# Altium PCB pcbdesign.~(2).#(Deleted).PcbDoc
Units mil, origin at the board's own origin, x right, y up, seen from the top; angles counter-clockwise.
Board outline 6000 x 4000 mil, 2 copper layers (Top Layer, Bottom Layer); 15 components, 13 nets, 60 pads, 0 vias.
Unrouted connection lines stored in the file: 20.
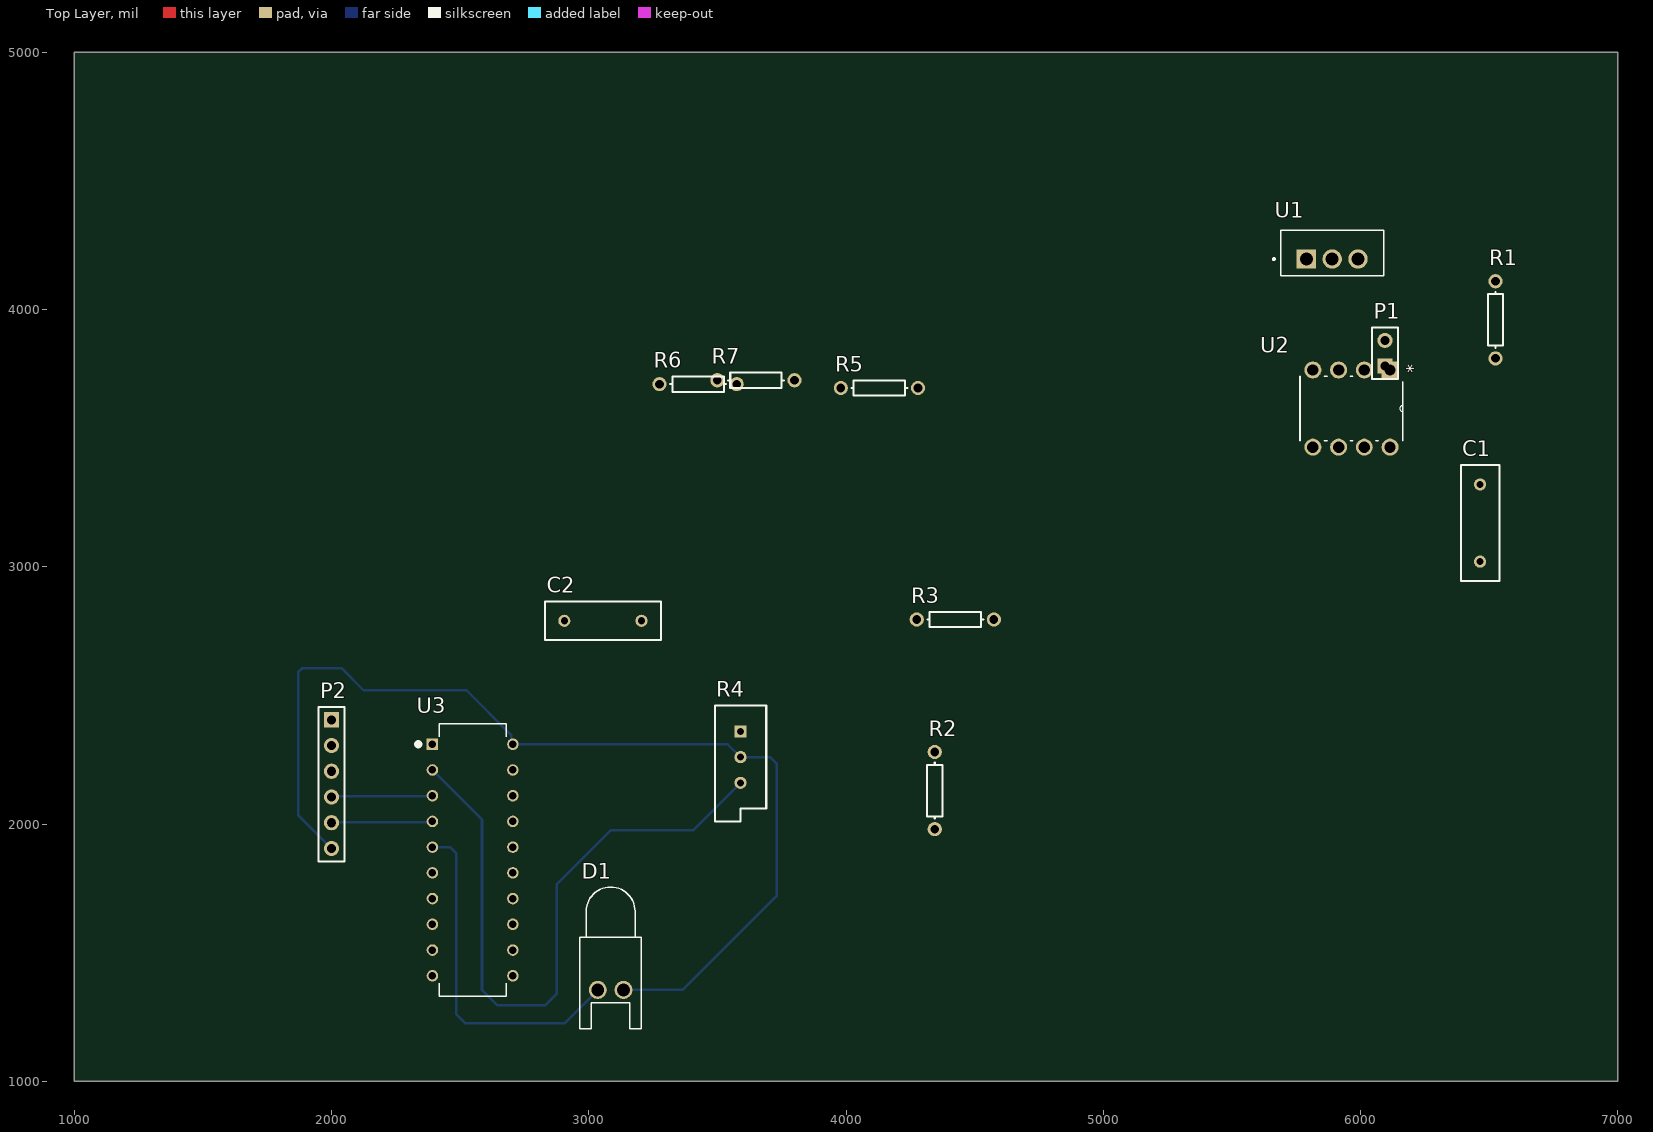
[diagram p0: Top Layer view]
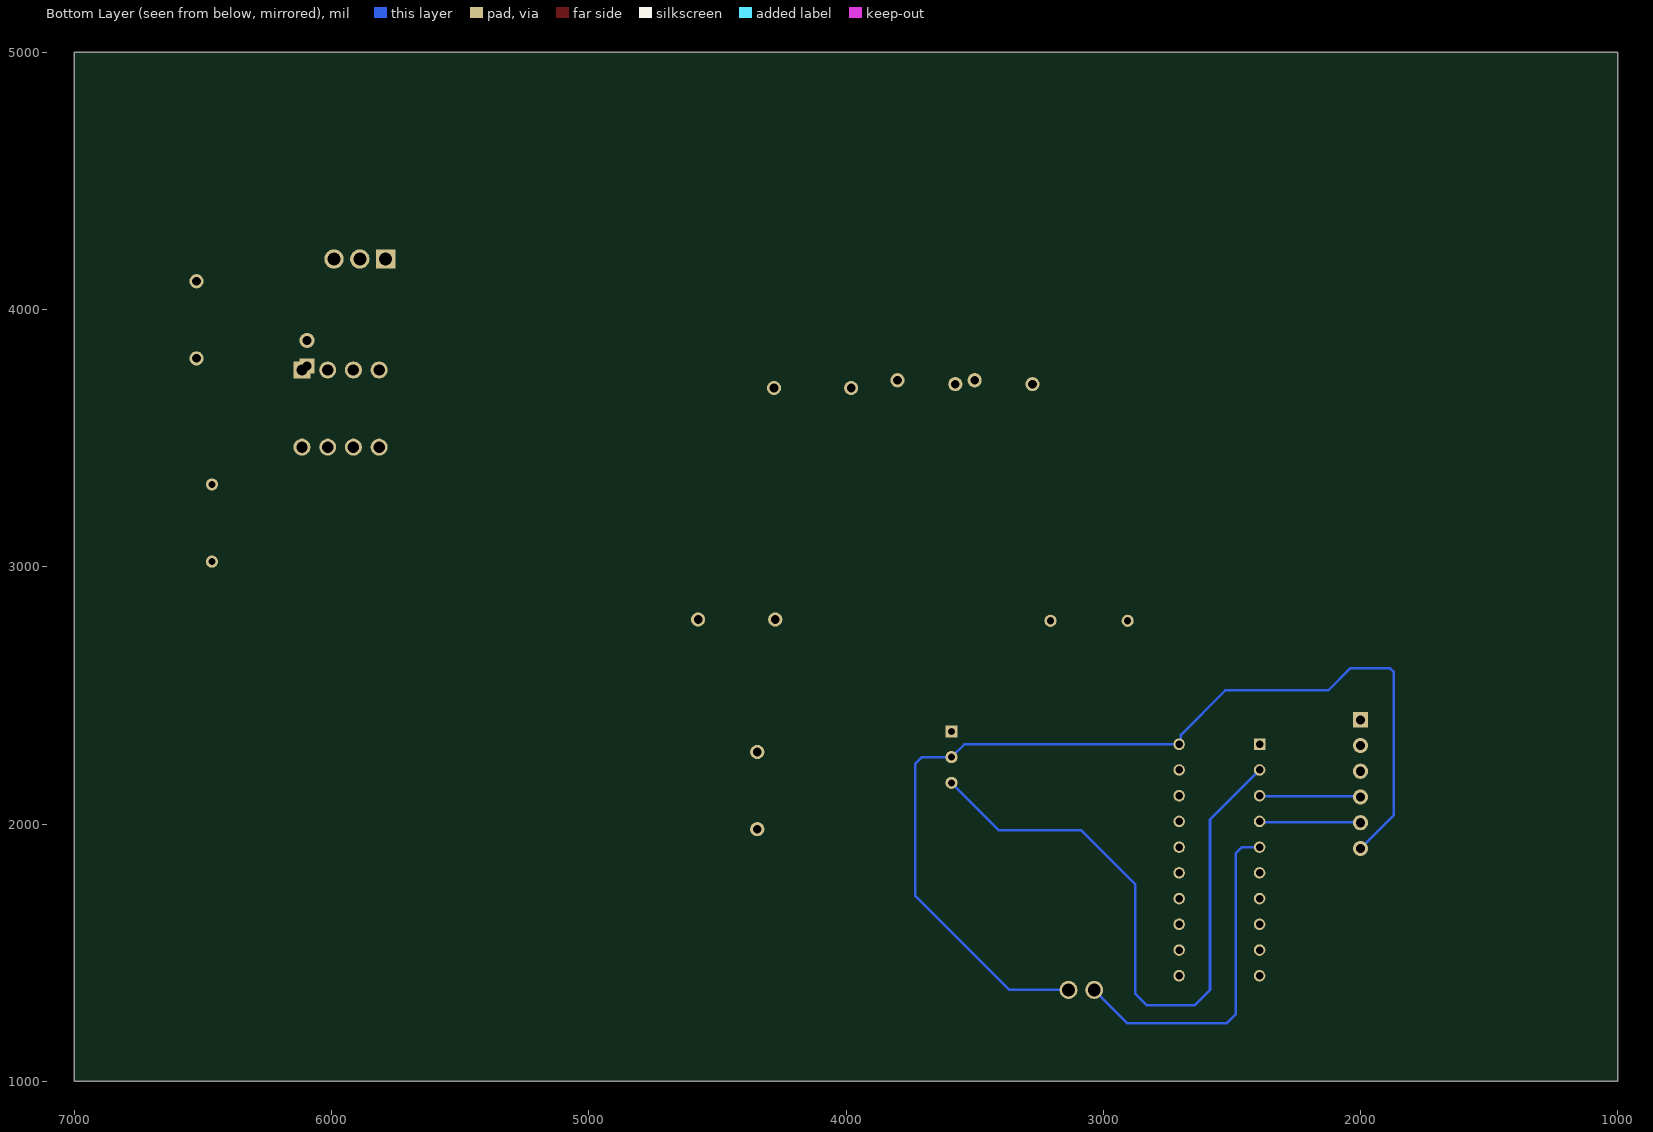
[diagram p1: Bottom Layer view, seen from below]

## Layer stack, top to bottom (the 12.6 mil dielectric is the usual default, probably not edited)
Top Solder: solder mask 0.4, Solder Resist, Dk 3.5
Top Layer: signal copper 1.4
Dielectric 1: dielectric 12.6, FR-4, Dk 4.8
Bottom Layer: signal copper 1.4
Bottom Solder: solder mask 0.4, Solder Resist, Dk 3.5

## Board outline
1000,1000 7000,1000 7000,5000 1000,5000

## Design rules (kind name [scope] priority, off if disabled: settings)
Clearance [All] p1: gap=10 ignorepadtopadclearanceinfootprint=FALSE except(0: Arc-Hole Track-Hole SMDPad-Hole THPad-Hole Via-Hole Fill-Hole Poly-Hole Region-Hole Text-Hole)
PolygonConnect [All] p1: connectstyle=Relief reliefconductorwidth=10 reliefentries=4 polygonreliefangle="90 Angle" airgapwidth=10
RoutingVias [All] p1: holewidth=28 width=50 viastyle="Through Hole" minholewidth=28 minwidth=50 maxholewidth=28 maxwidth=50
SolderMaskExpansion [All] p1: expansion=4 istentingtop=FALSE
Width [All] p1: maxlimit=10 minlimit=10 preferedwidth=10
30 further rules are at their usual default settings.

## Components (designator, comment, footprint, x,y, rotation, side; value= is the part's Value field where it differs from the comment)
C1 "Cap" RAD-0.3 6465,3170 r270 top value=1nF
C2 "Cap" RAD-0.3 3055,2790 r180 top value=1nF
D1 "LED0" LED-0 3085,1355 r180 top
P1 "Header 2" HDR1X2 6095,3780 r90 top
P2 "Header 6" HDR1X6 2000,2405 r270 top
R1 "Res1" AXIAL-0.3 6525,3960 r90 top value=100K
R2 "Res1" AXIAL-0.3 4345,2130 r90 top value=47K
R3 "Res1" AXIAL-0.3 4425,2795 r180 top value=1K
R4 "RPot" VR5 3590,2260 r270 top value=1K
R5 "Res1" AXIAL-0.3 4130,3695 r180 top value=100K
R6 "Res1" AXIAL-0.3 3425,3710 r0 top value=100K
R7 "Res1" AXIAL-0.3 3650,3725 r180 top value=47K
U1 "LD1117V33" TO255P1020X450X1968-3 5890,4220 r0 top
U2 "LM741CN" DIP254P762X508-8 5815,3465 r270 top
U3 "MSP430G2553IN20" DIP794W45P254L2692H508Q20 2548.7,1860 r0 top

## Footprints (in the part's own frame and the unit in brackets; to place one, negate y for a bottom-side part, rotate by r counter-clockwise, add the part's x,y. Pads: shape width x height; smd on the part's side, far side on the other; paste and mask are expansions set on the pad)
AXIAL-0.3 [mm] "Axial Device, Thru-Hole; 2 Leads; 0.3 in Pin Spacing"
  round 1.4 hole 0.85: 1(-3.81,0) 2(3.81,0)
  silkscreen extent -2.77,-0.76 2.77,0.76
DIP254P762X508-8 [mil]
  rect 66x66 hole 44: 1(-300,300)
  round 66 hole 44: 2(-300,200) 3(-300,100) 4(-300,0) 5(0,0) 6(0,100) 7(0,200) 8(0,300)
  silkscreen extent -275,-50 -25,350, body extent -189,-215 189,215, height 200
DIP794W45P254L2692H508Q20 [mm]
  rect 1.14x1.14 hole 0.74: 1(-3.97,11.43)
  round 1.14 hole 0.74: 2(-3.97,8.89) 3(-3.97,6.35) 4(-3.97,3.81) 5(-3.97,1.27) 6(-3.97,-1.27) 7(-3.97,-3.81) 8(-3.97,-6.35) 9(-3.97,-8.89) 10(-3.97,-11.43) 11(3.97,-11.43) 12(3.97,-8.89) 13(3.97,-6.35) 14(3.97,-3.81) 15(3.97,-1.27) 16(3.97,1.27) 17(3.97,3.81) 18(3.97,6.35) 19(3.97,8.89) 20(3.97,11.43)
  silkscreen extent -5.57,-13.46 3.3,13.46
HDR1X2 [mm] "Connector; Header; 2 Position"
  rect 1.5x1.5 hole 0.9: 1(0,0)
  round 1.5 hole 0.9: 2(2.54,0)
  silkscreen extent -1.27,-1.27 3.81,1.27
HDR1X6 [mm] "Connector; Header; 6 Position"
  rect 1.5x1.5 hole 0.9: 1(0,0)
  round 1.5 hole 0.9: 2(2.54,0) 3(5.08,0) 4(7.62,0) 5(10.16,0) 6(12.7,0)
  silkscreen extent -1.27,-1.27 13.97,1.27
LED-0 [mil] "LED; 2 Leads"
  round 70 hole 50: 1(50,0) 2(-50,0)
  silkscreen extent -120,-400 120,150
RAD-0.3 [mm] "Radial Cap, Thru-Hole; 2 Leads; 0.3 in Pin Spacing"
  round 1.2 hole 0.7: 1(-3.81,0) 2(3.81,0)
  silkscreen extent -5.71,-1.91 5.71,1.91
TO255P1020X450X1968-3 [mm]
  rect 1.91x1.91 / inner round 1.91 / far side rect 1.91x1.91 hole 1.27: 1(-2.55,-0.605)
  round 1.91 hole 1.27: 2(0,-0.605) 3(2.55,-0.605)
  silkscreen extent -5.85,-2.25 5.1,2.25, body extent -4.98,-1.76 4.98,2.69, height 19.68
VR5 [mm] "Thru-Hole; 3 Leads"
  rect 1.2x1.2 hole 0.7: 1(-2.54,0)
  round 1.2 hole 0.7: 2(0,0) 3(2.54,0)
  silkscreen extent -5.08,-2.54 6.35,2.54

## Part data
C1 C2: "Capacitor"
D1: "Typical INFRARED GaAs LED"
P1: "Header, 2-Pin"
P2: "Header, 6-Pin"
R1 R2 R3 R5 R6 R7: "Resistor"
R4: "Potentiometer"
U1: "Linear Voltage Regulator IC Positive Fixed 1 Output 800mA TO-220AB", Package="TO-220-3 ON Semiconductor"
U2: "General Purpose Amplifier 1 Circuit 8-DIP", Package="DIP-8 ON Semiconductor"
U3: "MSP430G2x53, MSP430G2x13 Mixed Signal Microcontroller 20-PDIP -40 to 85", Package=None

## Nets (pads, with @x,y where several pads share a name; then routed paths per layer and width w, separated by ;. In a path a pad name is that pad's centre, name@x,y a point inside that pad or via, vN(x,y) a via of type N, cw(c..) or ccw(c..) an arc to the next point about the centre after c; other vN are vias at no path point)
GND: C2.2 D1.2 P1.2 P2.6 R4.2 R6.1 R7.2 U1.1 U3.20 | length 4037.1
  Bottom Layer w10: P2.6 1870,2035 1870,2590 1885,2605 2040,2605 2125,2520 2525,2520 2698.33,2346.67 2698.33,2316.67 U3.20 3540,2310 R4.2 3705,2260 3730,2235 3730,1720 3365,1355 D1.2
NetC1_1: C1.1 R1.1
NetC1_2: C1.2 C2.1 R6.2 U2.3
NetD1_1: D1.1 U3.5 | length 1346.3
  Bottom Layer w10: U3.5 2460,1910 2485,1885 2485,1260 2520,1225 2905,1225 D1.1
NetP1_1: P1.1 U1.3 U2.7
NetP2_4: P2.4 U3.3 | length 394.5
  Bottom Layer w10: P2.4 2002.5,2107.5 2389.9,2107.5 U3.3
NetP2_5: P2.5 U3.4 | length 394.5
  Bottom Layer w10: P2.5 2002.5,2007.5 2389.9,2007.5 U3.4
NetR1_2: R1.2 R3.2 R5.1 U2.6
NetR2_1: R2.1 U3.16
NetR2_2: R2.2 U1.2 U3.1
NetR3_1: R3.1 R4.1
NetR4_3: R4.3 U3.2 | length 2571.9
  Bottom Layer w10: U3.2 2585,2017.4 2585,1355 2645,1295 2830,1295 2875,1340 2875,1765 3085,1975 3405,1975 R4.3
NetR5_2: R5.2 R7.1 U2.2
pads on no net: P2.1 P2.2 P2.3 U2.1 U2.4 U2.5 U2.8 U3.6 U3.7 U3.8 U3.9 U3.10 U3.11 U3.12 U3.13 U3.14 U3.15 U3.17 U3.18 U3.19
